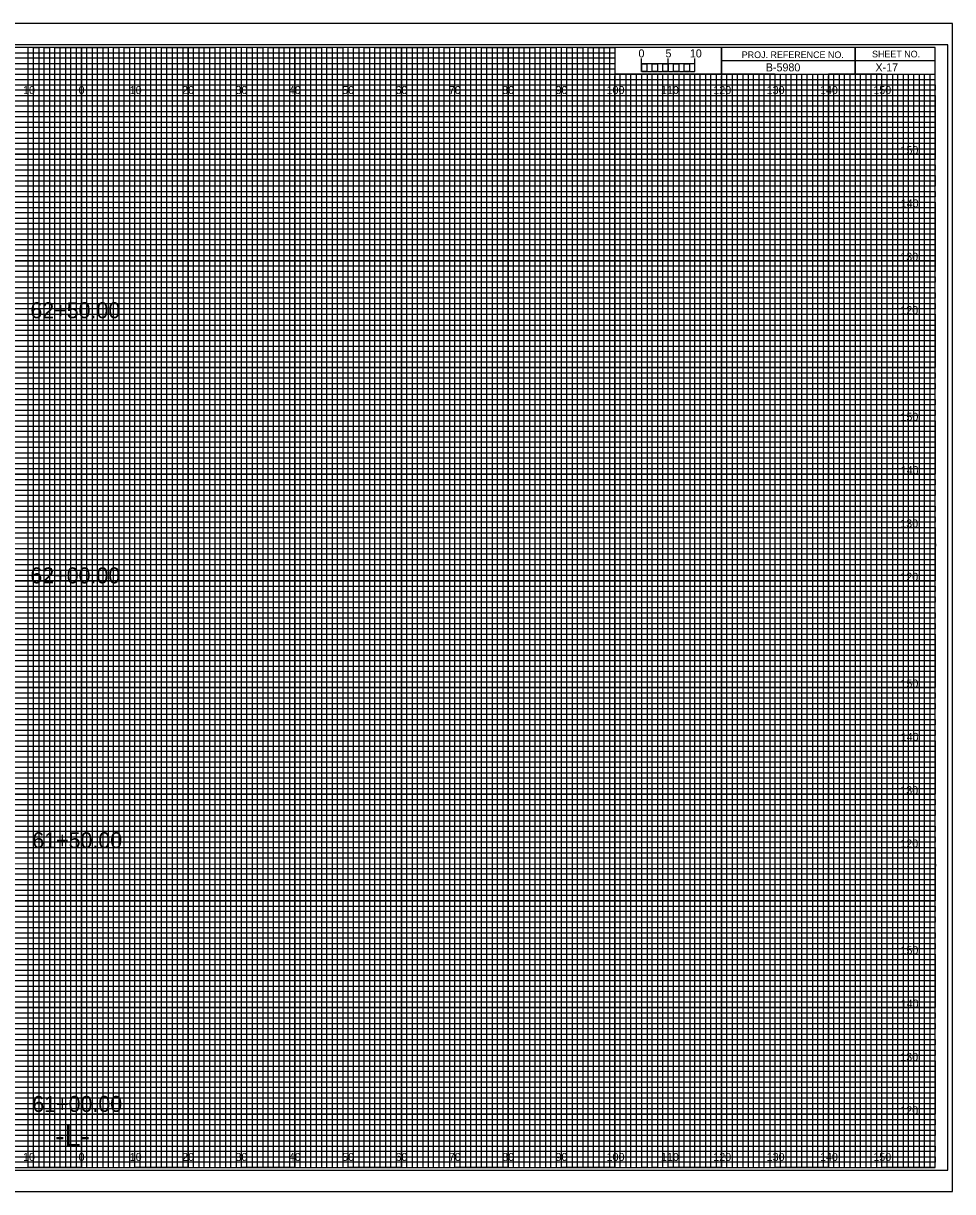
# Model space of a CAD drawing. Extents: x -13 to 323, y -5 to 1754.
# Drawn here: x 149.1 to 323.3, y 215.5 to 434.5 of the extents above; entities that cross this region are included whole.
import ezdxf

# ---------------------------------------------------------------- set-up
doc = ezdxf.new("R2010")
doc.units = 0
for name, color, linetype in [('Exist Cross Section Cell', 7, 'Continuous'), ('Exist XS Center Line Elevation Label', 7, 'Continuous'), ('Exist XS Ground Line', 7, 'Continuous'), ('Prop CMT Bridge Metal Rail', 7, 'Continuous'), ('Prop CMT Pvmt Course 1', 7, 'Continuous'), ('Prop CMT Pvmt Course 2', 7, 'Continuous'), ('Prop CMT Pvmt Course 3', 7, 'Continuous'), ('Prop CMT Pvmt Surface', 7, 'Continuous'), ('Prop CMT Pvmt Surface Shoulder', 7, 'Continuous'), ('Prop CMT Shld Paved Course 1', 7, 'Continuous'), ('Prop CMT Shld Paved Course 2', 7, 'Continuous'), ('Prop CMT Shld Paved Course 3', 7, 'Continuous'), ('Prop CMT Slope Grass', 7, 'Continuous'), ('Prop CMT Subgrade Earthwork', 7, 'Continuous'), ('Prop XS Shear Point Element', 7, 'Continuous'), ('Prop XS Shear Point Label', 7, 'Continuous'), ('Scratch_Level_1', 7, 'Continuous')]:
    doc.layers.add(name, color=color, linetype=linetype)

msp = doc.modelspace()

# ---------------------------------------------------------------- linework, layer by layer
at = {"layer": 'Exist XS Center Line Elevation Label'}
for points in [[(145, 220), (155, 220), (155, 430), (165, 430), (165, 220), (175, 220), (175, 430), (185, 430), (185, 220), (195, 220), (195, 430), (205, 430), (205, 220), (215, 220), (215, 430), (225, 430), (225, 220), (235, 220), (235, 430), (245, 430), (245, 220), (255, 220), (255, 430), (259.93, 430), (260, 430), (260, 425), (264.99, 425), (264.99, 220), (275, 220), (275, 425), (285, 425), (285, 220), (295, 220), (295, 425), (305, 425), (305, 220), (315, 220), (315, 425)], [(0, 425), (275, 425)], [(0, 405), (320, 405), (320, 415), (0, 415)], [(0, 385), (320, 385), (320, 395), (0, 395)], [(0, 365), (320, 365), (320, 375), (0, 375)], [(0, 345), (320, 345), (320, 355), (0, 355)], [(0, 325), (320, 325), (320, 335), (0, 335)], [(0, 305), (320, 305), (320, 315), (0, 315)], [(0, 285), (320, 285), (320, 295), (0, 295)], [(0, 265), (320, 265), (320, 275), (0, 275)], [(0, 245), (320, 245), (320, 255), (0, 255)], [(0, 225), (320, 225), (320, 235), (0, 235)]]:
    msp.add_lwpolyline(points, dxfattribs=at)
at = {"layer": 'Exist XS Ground Line'}
for p, q in [((150, 430), (140, 430)), ((150, 220), (150, 430)), ((170, 430), (160, 430)), ((160, 430), (160, 220)), ((170, 220), (170, 430)), ((190, 430), (180, 430)), ((180, 430), (180, 220)), ((190, 220), (190, 430)), ((210, 430), (200, 430)), ((200, 430), (200, 220)), ((210, 220), (210, 430)), ((230, 430), (220, 430)), ((220, 430), (220, 220)), ((230, 220), (230, 430)), ((250, 430), (240, 430)), ((240, 430), (240, 220)), ((250, 220), (250, 430)), ((260, 430), (260, 220)), ((270, 220), (270, 425)), ((290, 425), (280, 425)), ((280, 425), (280, 220)), ((290, 220), (290, 425)), ((310, 425), (300, 425)), ((300, 425), (300, 220)), ((310, 220), (310, 425)), ((160, 220), (150, 220)), ((180, 220), (170, 220)), ((200, 220), (190, 220)), ((220, 220), (210, 220)), ((240, 220), (230, 220)), ((260, 220), (250, 220)), ((280, 220), (270, 220)), ((300, 220), (290, 220)), ((320, 220), (310, 220)), ((320, 220), (320, 220))]:
    msp.add_line(p, q, dxfattribs=at)
for points in [[(0, 420), (320, 420), (320, 410), (0, 410)], [(0, 400), (320, 400), (320, 390), (0, 390)], [(0, 380), (320, 380), (320, 370), (0, 370)], [(0, 360), (320, 360), (320, 350), (0, 350)], [(0, 340), (320, 340), (320, 330), (0, 330)], [(0, 320), (320, 320), (320, 310), (0, 310)], [(0, 300), (320, 300), (320, 290), (0, 290)], [(0, 280), (320, 280), (320, 270), (0, 270)], [(0, 260), (320, 260), (320, 250), (0, 250)], [(0, 240), (320, 240), (320, 230), (0, 230)]]:
    msp.add_lwpolyline(points, dxfattribs=at)
at = {"layer": 'Prop CMT Pvmt Course 2'}
for p, q in [((265, 425.49), (265, 427.9)), ((265, 426.9), (265, 427.9)), ((270, 425.49), (270, 427.9)), ((275, 425.49), (275, 427.9)), ((275, 426.9), (275, 427.9))]:
    msp.add_line(p, q, dxfattribs=at)
for points in [[(275, 426.9), (265, 426.9), (265, 425.49), (275, 425.49)], [(265, 426.9), (266, 426.9), (266, 425.49), (265, 425.49)], [(267, 426.9), (268, 426.9), (268, 425.49), (267, 425.49)], [(269, 426.9), (270, 426.9), (270, 425.49), (269, 425.49)], [(271, 426.9), (272, 426.9), (272, 425.49), (271, 425.49)], [(273, 426.9), (274, 426.9), (274, 425.49), (273, 425.49)]]:
    msp.add_lwpolyline(points, close=True, dxfattribs=at)
at = {"layer": 'Prop CMT Pvmt Course 3'}
msp.add_lwpolyline([(-13.4, 215.5), (323.3, 215.5), (323.3, 434.5), (-13.4, 434.5)], close=True, dxfattribs=at)
at = {"layer": 'Prop CMT Pvmt Surface'}
for p, q in [((150, 220), (150, 430)), ((160, 220), (160, 430)), ((170, 220), (170, 430)), ((180, 220), (180, 430)), ((190, 220), (190, 430)), ((200, 220), (200, 430)), ((210, 220), (210, 430)), ((220, 220), (220, 430)), ((230, 220), (230, 430)), ((240, 220), (240, 430)), ((250, 220), (250, 430)), ((260, 220), (260, 424.69)), ((270, 220), (270, 424.69)), ((280, 220), (280, 424.69)), ((290, 220), (290, 424.69)), ((300, 220), (300, 424.69)), ((310, 220), (310, 424.69)), ((0, 420), (320, 420)), ((0, 410), (320, 410)), ((0, 400), (320, 400)), ((0, 390), (320, 390)), ((0, 380), (320, 380)), ((0, 370), (320, 370)), ((0, 360), (320, 360)), ((0, 350), (320, 350)), ((0, 340), (320, 340)), ((0, 330), (320, 330)), ((0, 320), (320, 320)), ((0, 310), (320, 310)), ((0, 300), (320, 300)), ((0, 290), (320, 290)), ((0, 280), (320, 280)), ((0, 270), (320, 270)), ((0, 260), (320, 260)), ((0, 250), (320, 250)), ((0, 240), (320, 240)), ((0, 230), (320, 230))]:
    msp.add_line(p, q, dxfattribs=at)
at = {"layer": 'Prop CMT Pvmt Surface Shoulder'}
for p, q in [((323.3, 434.5), (-13.4, 434.5)), ((-13.4, 215.5), (323.3, 215.5))]:
    msp.add_line(p, q, dxfattribs=at)
at = {"layer": 'Prop CMT Shld Paved Course 1'}
for p, q in [((0, 429), (260, 429)), ((260, 427.98), (0, 427.98)), ((260, 429), (260, 427.98)), ((0, 427), (260, 427)), ((260, 425.89), (0, 425.89)), ((260, 427), (260, 425.89)), ((0, 424), (320, 424))]:
    msp.add_line(p, q, dxfattribs=at)
for points in [[(0, 423), (270, 423), (320, 423), (320, 422), (0, 422)], [(0, 421), (320, 421), (320, 419), (0, 419)], [(0, 418), (320, 418), (320, 417), (0, 416.98)], [(0, 416), (320, 416), (320, 414), (0, 414)], [(0, 413), (320, 413), (320, 412), (0, 412)], [(0, 411), (320, 411), (320, 409), (0, 409)], [(0, 408), (320, 408), (320, 407), (0, 407)], [(0, 406), (320, 406), (320, 404), (0, 404)], [(0, 403), (320, 403), (320, 402), (0, 402)], [(0, 401), (320, 401), (320, 399), (0, 399)], [(0, 398), (320, 398), (320, 397), (0, 397)], [(0, 396), (320, 396), (320, 393.95), (320, 393), (320, 392), (0, 392)], [(0, 394), (320, 394), (320, 393), (0, 393)], [(0, 391), (320, 391), (320, 389), (0, 389.03)], [(0, 389.03), (320, 389), (320, 388), (0, 388)], [(0, 387), (320, 387), (320, 386), (0, 386)], [(0, 384), (320, 384), (320, 383), (0, 383)], [(0, 382), (320, 382), (320, 381), (0, 381)], [(-0.07, 378.89), (320, 378.89), (320, 377.88), (-0.07, 377.88)], [(0, 377), (320, 377), (320, 376), (0, 376)], [(0, 374), (320, 374), (320, 373), (0, 373)], [(0, 372), (320, 372), (320, 371), (0, 371)], [(0, 369), (320, 369), (320, 368), (0, 368)], [(0, 367), (320, 367), (320, 366), (0, 366)], [(0, 364), (320, 364), (320, 363), (0, 363)], [(0, 362), (320, 362), (320, 361), (0, 361)], [(0, 359), (320, 359), (319.99, 357.98), (0, 358)], [(0, 357), (320, 357), (320, 356), (0, 356)], [(0, 354), (320, 354), (320, 353), (0, 353)], [(0, 352), (320, 352), (320, 351), (0, 351)], [(0, 349), (320, 349), (320, 348), (0, 348)], [(0, 347), (320, 347), (320, 346), (0, 346)], [(0, 344), (320, 344), (320, 343), (0, 343)], [(0, 342), (320, 342), (320, 341), (0, 341)], [(0, 339), (320, 339), (320, 338), (0, 338)], [(0, 336.99), (320.07, 336.91), (320, 336), (0, 336)], [(0, 334), (320, 334), (320, 333), (0, 333)], [(0, 332), (320, 332), (320, 331), (0, 331)], [(0, 329), (320, 329), (320, 328), (0, 328)], [(0, 327), (320, 327), (320, 326), (0, 326)], [(0, 324), (320, 324), (320, 323), (0, 323)], [(0, 322), (320, 322), (320, 321), (0, 321)], [(0, 319), (320, 319), (320, 318), (0, 318)], [(0, 317), (320, 317), (320, 316), (0, 316)], [(0, 314), (320, 314), (320, 313), (0, 313)], [(0, 312), (320, 312), (320, 311), (0, 311)], [(0, 309), (320, 309), (320, 308), (0, 308)], [(0, 307), (320, 307), (320, 306), (0, 306)], [(0, 304), (320, 304), (320, 303), (0, 303)], [(0, 302), (320, 302), (320, 301), (0, 301)], [(0, 299), (320, 299), (319.99, 297.98), (0, 298)], [(0, 297), (320, 297), (320, 296), (0, 296)], [(0, 294), (320, 294), (320, 293), (0, 293)], [(0, 292), (320, 292), (320, 291), (0, 291)], [(0, 289), (320, 289), (320, 288), (0, 288)], [(0, 287), (320, 287), (320, 286), (0, 286)], [(0, 284), (320, 284), (320, 283), (0, 283)], [(0, 282), (320, 282), (320, 281), (0, 281)], [(0, 279), (320, 279), (320, 278), (0, 278)], [(0, 276.99), (320.07, 276.91), (320, 276), (0, 276)], [(0, 274), (320, 274), (320, 273), (0, 273)], [(0, 272), (320, 272), (320, 271), (0, 271)], [(0, 269), (320, 269), (320, 268), (0, 268)], [(0, 267), (320, 267), (320, 266), (0, 266)], [(0, 264), (320, 264), (320, 263), (0, 263)], [(0, 262), (320, 262), (320, 261), (0, 261)], [(0, 259), (320, 259), (320, 258), (0, 258)], [(0, 257), (320, 257), (320, 256), (0, 256)], [(0, 254), (320, 254), (320, 253), (0, 253)], [(0, 252), (320, 252), (320, 251), (0, 251)], [(0, 249), (320, 249), (320, 248), (0, 248)], [(0, 247), (320, 247), (320, 246), (0, 246)], [(0, 244), (320, 244), (320, 243), (0, 243)], [(0, 242), (320, 242), (320, 241), (0, 241)], [(0, 239), (320, 239), (320, 238), (0, 238)], [(0, 237), (320, 237), (320, 236), (0, 236)], [(0, 234), (320, 234), (320, 233), (0, 233)], [(0, 232), (320, 232), (320, 231), (0, 231)], [(0, 229), (320, 229), (320, 228), (0, 228)], [(0, 227), (320, 227), (320, 226), (0, 226)], [(0, 224), (320, 224), (320, 223), (0, 223)], [(0, 222), (320, 222), (320, 221), (0, 221)]]:
    msp.add_lwpolyline(points, dxfattribs=at)
at = {"layer": 'Prop CMT Shld Paved Course 2'}
for p, q in [((305, 430), (305, 425)), ((305, 425), (305, 430)), ((280, 427.5), (280, 425)), ((320, 427.49), (280, 427.49)), ((280, 425), (320, 425))]:
    msp.add_line(p, q, dxfattribs=at)
for points in [[(320, 430), (0, 430), (0, 220), (320, 220)], [(280, 430), (260, 430), (260, 425.03), (280, 425.03)], [(320, 430), (280, 430), (280, 425), (320, 425)]]:
    msp.add_lwpolyline(points, close=True, dxfattribs=at)
at = {"layer": 'Prop CMT Shld Paved Course 3'}
for p, q in [((267, 425), (266.01, 425)), ((266.01, 425), (266.01, 220)), ((267, 220), (267, 425)), ((269, 425), (268, 425)), ((268, 425), (268, 220)), ((269, 220), (269, 425)), ((266.01, 220), (265, 220)), ((268, 220), (267, 220))]:
    msp.add_line(p, q, dxfattribs=at)
for points in [[(150, 220), (151, 220), (151, 430), (152, 430), (152, 220)], [(152, 220), (153, 220), (153, 430), (154, 430), (154, 220)], [(155, 220), (156, 220), (156, 430), (157, 430), (157, 220)], [(157, 220), (158, 220), (158, 430), (159, 430), (159, 220)], [(160, 220), (161, 220), (161, 430), (162, 430), (162, 220)], [(162, 220), (163, 220), (163, 430), (164, 430), (164, 220)], [(165, 220), (166, 220), (166, 430), (167, 430), (167, 220)], [(167, 220), (168, 220), (168, 430), (169, 430), (169, 220)], [(170, 220), (171, 220), (171, 430), (172, 430), (172, 220)], [(172, 220), (173, 220), (173, 430), (174, 430), (174, 220)], [(175, 220), (176, 220), (176, 430), (177, 430), (177, 220)], [(177, 220), (178, 220), (178, 430), (179, 430), (179, 220)], [(180, 220), (181, 220), (181, 430), (182, 430), (182, 220)], [(182, 220), (183, 220), (183, 430), (184, 430), (184, 220)], [(185, 220), (186, 220), (186, 430), (187, 430), (187, 220)], [(187, 220), (188, 220), (188, 430), (189, 430), (189, 220)], [(190, 220), (191, 220), (191, 430), (192, 430), (192, 220)], [(192, 220), (193, 220), (193, 430), (194, 430), (194, 220)], [(195, 220), (196, 220), (196, 430), (197, 430), (197, 220)], [(197, 220), (198, 220), (198, 430), (199, 430), (199, 220)], [(200, 220), (201, 220), (201, 430), (202, 430), (202, 220)], [(202, 220), (203, 220), (203, 430), (204, 430), (204, 220)], [(205, 220), (206, 220), (206, 430), (207, 430), (207, 220)], [(207, 220), (208, 220), (208, 430), (209, 430), (209, 220)], [(210, 220), (211, 220), (211, 430), (212, 430), (212, 220)], [(212, 220), (213, 220), (213, 430), (214, 430), (214, 220)], [(215, 220), (216, 220), (216, 430), (217, 430), (217, 220)], [(217, 220), (218, 220), (218, 430), (219, 430), (219, 220)], [(220, 220), (221, 220), (221, 430), (222, 430), (222, 220)], [(222, 220), (223, 220), (223, 430), (224, 430), (224, 220)], [(225, 220), (226, 220), (226, 430), (227, 430), (227, 220)], [(227, 220), (228, 220), (228, 430), (229, 430), (229, 220)], [(230, 220), (231, 220), (231, 430), (232, 430), (232, 220)], [(232, 220), (233, 220), (233, 430), (234, 430), (234, 220)], [(235, 220), (236, 220), (236, 430), (237, 430), (237, 220)], [(237, 220), (238, 220), (238, 430), (239, 430), (239, 220)], [(240, 220), (241, 220), (241, 430), (242, 430), (242, 220)], [(242, 220), (243, 220), (243, 430), (244, 430), (244, 220)], [(245, 220), (246, 220), (246, 430), (247, 430), (247, 220)], [(247, 220), (248, 220), (248, 430), (249, 430), (249, 220)], [(250, 220), (251, 220), (251, 430), (252, 430), (252, 220)], [(252, 220), (253, 220), (253, 430), (254, 430), (254, 220)], [(255, 220), (256, 220), (256, 430), (257, 430), (257, 220)], [(257, 220), (258, 220), (258, 430), (259, 430), (259, 220)], [(260, 220), (261, 220), (261, 425), (262.02, 425), (262.02, 220)], [(262, 220), (263, 220), (263, 425), (263.99, 425), (263.99, 220)], [(270, 220), (270.98, 220), (270.98, 425), (272, 425), (272, 220)], [(272, 220), (273, 220), (273, 425), (274.05, 425), (274.05, 220)], [(275, 220), (276, 220), (276, 425), (277, 425), (277, 220)], [(277, 220), (278, 220), (278, 425), (279, 425), (279, 220)], [(280, 220), (281, 220), (281, 425), (282, 425), (282, 220)], [(282, 220), (283, 220), (283, 425), (284, 425), (284, 220)], [(285, 220), (286, 220), (286, 425), (287, 425), (287, 220)], [(287, 220), (288, 220), (288, 425), (289, 425), (289, 220)], [(290, 220), (291, 220), (291, 425), (292, 425), (292, 220)], [(292, 220), (293, 220), (293, 425), (294, 425), (294, 220)], [(295, 220), (296, 220), (296, 425), (297, 425), (297, 220)], [(297, 220), (298, 220), (298, 425), (299, 425), (299, 220)], [(300, 220), (301, 220), (301, 425), (302, 425), (302, 220)], [(302, 220), (303, 220), (303, 425), (304, 425), (304, 220)], [(305, 220), (306, 220), (306, 425), (307, 425), (307, 220)], [(307, 220), (308, 220), (308, 425), (309, 425), (309, 220)], [(310, 220), (311, 220), (311, 425), (312, 425), (312, 220)], [(312, 220), (313, 220), (313, 425), (314, 425), (314, 220)], [(315, 220), (316, 220), (316, 425), (317, 425), (317, 220)], [(317, 220), (318, 220), (318, 425), (319, 425), (319, 220)]]:
    msp.add_lwpolyline(points, dxfattribs=at)
at = {"layer": 'Prop CMT Subgrade Earthwork'}
msp.add_lwpolyline([(-10.8, 219.5), (322.4, 219.5), (322.4, 430.5), (-10.8, 430.5)], close=True, dxfattribs=at)

# ---------------------------------------------------------------- texts
at = {"layer": 'Exist Cross Section Cell'}
for s, p in [('10', (149.04, 421.25)), ('0', (159.45, 421.25)), ('0', (159.45, 421.25)), ('10', (169.04, 421.25)), ('20', (178.86, 421.25)), ('30', (188.86, 421.25)), ('40', (198.86, 421.25)), ('50', (208.86, 421.25)), ('60', (218.86, 421.25)), ('70', (228.86, 421.25)), ('80', (238.86, 421.25)), ('90', (248.86, 421.25)), ('100', (258.44, 421.25)), ('110', (268.62, 421.25)), ('120', (278.44, 421.25)), ('130', (288.44, 421.25)), ('140', (298.44, 421.25)), ('150', (308.44, 421.25)), ('10', (149.04, 221.25)), ('0', (159.45, 221.25)), ('0', (159.45, 221.25)), ('10', (169.04, 221.25)), ('20', (178.86, 221.25)), ('30', (188.86, 221.25)), ('40', (198.86, 221.25)), ('50', (208.86, 221.25)), ('60', (218.86, 221.25)), ('70', (228.86, 221.25)), ('80', (238.86, 221.25)), ('90', (248.86, 221.25)), ('100', (258.44, 221.25)), ('110', (268.62, 221.25)), ('120', (278.44, 221.25)), ('130', (288.44, 221.25)), ('140', (298.44, 221.25)), ('150', (308.44, 221.25))]:
    msp.add_text(s, height=1.5, dxfattribs=at).set_placement(p)
at = {"layer": 'Prop CMT Bridge Metal Rail'}
for s, p in [('5', (269.47, 428.12)), ('10', (274.04, 428.12))]:
    msp.add_text(s, height=1.5, dxfattribs=at).set_placement(p)
at = {"layer": 'Prop CMT Pvmt Course 1'}
for s, p in [('150', (313.52, 410)), ('140', (313.57, 400)), ('130', (313.49, 390)), ('120', (313.5, 380)), ('150', (313.52, 360)), ('140', (313.57, 350)), ('130', (313.49, 340)), ('120', (313.5, 330)), ('150', (313.52, 310)), ('140', (313.57, 300)), ('130', (313.49, 290)), ('120', (313.5, 280)), ('150', (313.52, 260)), ('140', (313.57, 250)), ('130', (313.49, 240)), ('120', (313.5, 230))]:
    msp.add_text(s, height=1.5, dxfattribs=at).set_placement(p)
at = {"layer": 'Prop CMT Pvmt Course 2'}
msp.add_text('0', height=1.5, dxfattribs=at).set_placement((264.41, 428.12))
at = {"layer": 'Prop CMT Shld Paved Course 2'}
for s, p in [('PROJ. REFERENCE NO.', (283.77, 427.99)), ('SHEET NO.', (308.19, 428.12))]:
    msp.add_text(s, height=1.25, dxfattribs=at).set_placement(p)
at = {"layer": 'Prop CMT Slope Grass'}
for s, p in [('62+50.00', (150.41, 379.22)), ('62+00.00', (150.41, 329.52)), ('61+50.00', (150.77, 279.87)), ('61+00.00', (150.77, 230.44))]:
    msp.add_text(s, height=3, dxfattribs=at).set_placement(p)
at = {"layer": 'Prop XS Shear Point Element'}
msp.add_text('-L-', height=4, dxfattribs=at).set_placement((155.06, 224))
at = {"layer": 'Prop XS Shear Point Label'}
msp.add_text('B-5980', height=1.5, dxfattribs=at).set_placement((288.28, 425.5))
at = {"layer": 'Scratch_Level_1'}
msp.add_text('X-17', height=1.5, dxfattribs=at).set_placement((308.83, 425.5))

doc.saveas('drawing.dxf')
